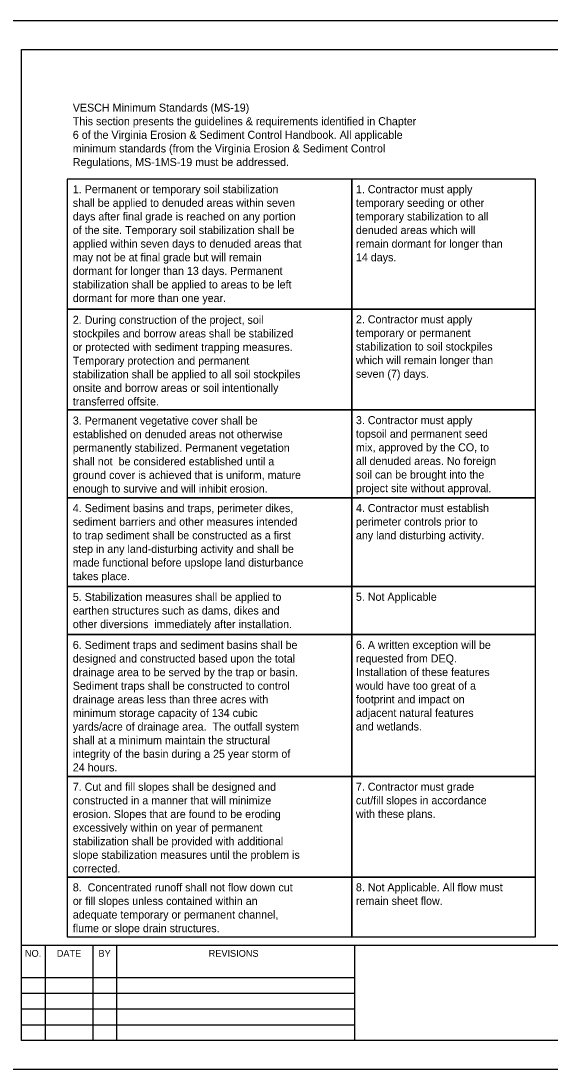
# Model space of a CAD drawing. Extents: x 20099.23 to 20103.48, y 6672.45 to 6674.37.
# Drawn here: x 20100.701 to 20101.165, y 6673.449 to 6674.366 of the extents above; entities that cross this region are included whole.
import ezdxf

# ---------------------------------------------------------------- set-up
doc = ezdxf.new("R2010")
doc.units = 0
for name, color, linetype in [('D_Details', 7, 'Continuous'), ('D_Plot_Shape', 7, 'Continuous'), ('D_Sheet', 7, 'Continuous')]:
    doc.layers.add(name, color=color, linetype=linetype)

msp = doc.modelspace()

# ---------------------------------------------------------------- linework, layer by layer
at = {"layer": 'D_Details'}
for points in [[(20100.99113, 6674.22774), (20100.74194, 6674.22774), (20100.74194, 6674.11395), (20100.99113, 6674.11395)], [(20101.15216, 6674.22774), (20100.99113, 6674.22774), (20100.99113, 6674.11395), (20101.15216, 6674.11395)], [(20100.99113, 6674.11395), (20100.74194, 6674.11395), (20100.74194, 6674.02578), (20100.99113, 6674.02578)], [(20101.15216, 6674.11395), (20100.99113, 6674.11395), (20100.99113, 6674.02578), (20101.15216, 6674.02578)], [(20100.99113, 6674.02578), (20100.74194, 6674.02578), (20100.74194, 6673.94888), (20100.99113, 6673.94888)], [(20101.15216, 6674.02578), (20100.99113, 6674.02578), (20100.99113, 6673.94888), (20101.15216, 6673.94888)], [(20100.99113, 6673.94888), (20100.74194, 6673.94888), (20100.74194, 6673.87127), (20100.99113, 6673.87127)], [(20101.15216, 6673.94888), (20100.99113, 6673.94888), (20100.99113, 6673.87127), (20101.15216, 6673.87127)], [(20100.99113, 6673.87127), (20100.74194, 6673.87127), (20100.74194, 6673.82925), (20100.99113, 6673.82925)], [(20101.15216, 6673.87127), (20100.99113, 6673.87127), (20100.99113, 6673.82925), (20101.15216, 6673.82925)], [(20100.99113, 6673.82925), (20100.74194, 6673.82925), (20100.74194, 6673.70518), (20100.99113, 6673.70518)], [(20101.15216, 6673.82925), (20100.99113, 6673.82925), (20100.99113, 6673.70518), (20101.15216, 6673.70518)], [(20100.99113, 6673.70518), (20100.74194, 6673.70518), (20100.74194, 6673.61724), (20100.99113, 6673.61724)], [(20101.15216, 6673.70518), (20100.99113, 6673.70518), (20100.99113, 6673.61724), (20101.15216, 6673.61724)], [(20100.99113, 6673.61724), (20100.74194, 6673.61724), (20100.74194, 6673.56499), (20100.99113, 6673.56499)], [(20101.15216, 6673.61724), (20100.99113, 6673.61724), (20100.99113, 6673.56499), (20101.15216, 6673.56499)]]:
    msp.add_lwpolyline(points, close=True, dxfattribs=at)
at = {"layer": 'D_Plot_Shape'}
msp.add_lwpolyline([(20102.06018, 6674.36597), (20100.64352, 6674.36597), (20100.64352, 6673.44931), (20102.06018, 6673.44931)], close=True, dxfattribs=at)
at = {"layer": 'D_Sheet'}
for p, q in [((20100.70185, 6673.55764), (20102.00185, 6673.55764)), ((20100.72269, 6673.55764), (20100.72269, 6673.47431)), ((20100.76435, 6673.55764), (20100.76435, 6673.47431)), ((20100.78519, 6673.55764), (20100.78519, 6673.47431)), ((20100.99352, 6673.55764), (20100.99352, 6673.47431)), ((20100.70185, 6673.52951), (20100.99352, 6673.52951)), ((20100.70185, 6673.51571), (20100.99352, 6673.51571)), ((20100.70185, 6673.50191), (20100.99352, 6673.50191)), ((20100.70185, 6673.48811), (20100.99352, 6673.48811))]:
    msp.add_line(p, q, dxfattribs=at)
msp.add_lwpolyline([(20100.70185, 6673.47431), (20100.70185, 6673.55764), (20100.70185, 6674.34097), (20102.00185, 6674.34097), (20102.00185, 6673.55764), (20102.00185, 6673.47431), (20100.70185, 6673.47431)], dxfattribs=at)

# ---------------------------------------------------------------- texts
at = {"layer": 'D_Details'}
for s, p in [('VESCH Minimum Standards (MS-19)', (20100.74688, 6674.28668)), ('This section presents the guidelines & requirements identified in Chapter ', (20100.74688, 6674.27478)), ('6 of the Virginia Erosion & Sediment Control Handbook. All applicable ', (20100.74688, 6674.26288)), ('minimum standards (from the Virginia Erosion & Sediment Control ', (20100.74688, 6674.25098)), ('Regulations, MS-1MS-19 must be addressed.', (20100.74688, 6674.23908)), ('1. Permanent or temporary soil stabilization ', (20100.74688, 6674.21531)), ('1. Contractor must apply ', (20100.99479, 6674.2153)), ('shall be applied to denuded areas within seven ', (20100.74688, 6674.20341)), ('temporary seeding or other ', (20100.99479, 6674.2034)), ('days after final grade is reached on any portion ', (20100.74688, 6674.19151)), ('temporary stabilization to all ', (20100.99479, 6674.1915)), ('of the site. Temporary soil stabilization shall be ', (20100.74688, 6674.17961)), ('denuded areas which will ', (20100.99479, 6674.1796)), ('applied within seven days to denuded areas that ', (20100.74688, 6674.16771)), ('remain dormant for longer than ', (20100.99479, 6674.1677)), ('may not be at final grade but will remain ', (20100.74688, 6674.15581)), ('14 days.', (20100.99479, 6674.1558)), ('dormant for longer than 13 days. Permanent ', (20100.74688, 6674.14391)), ('stabilization shall be applied to areas to be left ', (20100.74688, 6674.13201)), ('dormant for more than one year. ', (20100.74688, 6674.12011)), ('2. During construction of the project, soil ', (20100.74688, 6674.10108)), ('2. Contractor must apply ', (20100.99479, 6674.10151)), ('stockpiles and borrow areas shall be stabilized ', (20100.74688, 6674.08918)), ('temporary or permanent ', (20100.99479, 6674.08961)), ('or protected with sediment trapping measures. ', (20100.74688, 6674.07728)), ('stabilization to soil stockpiles ', (20100.99479, 6674.07771)), ('Temporary protection and permanent ', (20100.74688, 6674.06538)), ('which will remain longer than ', (20100.99479, 6674.06581)), ('stabilization shall be applied to all soil stockpiles ', (20100.74688, 6674.05348)), ('seven (7) days.', (20100.99479, 6674.05391)), ('onsite and borrow areas or soil intentionally ', (20100.74688, 6674.04158)), ('transferred offsite.', (20100.74688, 6674.02968)), ('3. Permanent vegetative cover shall be ', (20100.74688, 6674.01297)), ('3. Contractor must apply ', (20100.99479, 6674.01334)), ('established on denuded areas not otherwise ', (20100.74688, 6674.00107)), ('topsoil and permanent seed ', (20100.99479, 6674.00144)), ('permanently stabilized. Permanent vegetation ', (20100.74688, 6673.98917)), ('mix, approved by the CO, to ', (20100.99479, 6673.98954)), ('shall not  be considered established until a ', (20100.74688, 6673.97727)), ('all denuded areas. No foreign ', (20100.99479, 6673.97764)), ('ground cover is achieved that is uniform, mature ', (20100.74688, 6673.96537)), ('soil can be brought into the ', (20100.99479, 6673.96574)), ('enough to survive and will inhibit erosion.', (20100.74688, 6673.95347)), ('project site without approval. ', (20100.99479, 6673.95384)), ('4. Sediment basins and traps, perimeter dikes, ', (20100.74688, 6673.9364)), ('4. Contractor must establish ', (20100.99479, 6673.93644)), ('sediment barriers and other measures intended ', (20100.74688, 6673.9245)), ('perimeter controls prior to ', (20100.99479, 6673.92454)), ('to trap sediment shall be constructed as a first ', (20100.74688, 6673.9126)), ('any land disturbing activity.', (20100.99479, 6673.91264)), ('step in any land-disturbing activity and shall be ', (20100.74688, 6673.9007)), ('made functional before upslope land disturbance ', (20100.74688, 6673.8888)), ('takes place. ', (20100.74688, 6673.8769)), ('5. Stabilization measures shall be applied to ', (20100.74688, 6673.85873)), ('5. Not Applicable', (20100.99479, 6673.85883)), ('earthen structures such as dams, dikes and ', (20100.74688, 6673.84683)), ('other diversions  immediately after installation. ', (20100.74688, 6673.83493)), ('6. A written exception will be ', (20100.99479, 6673.81681)), ('6. Sediment traps and sediment basins shall be ', (20100.74688, 6673.81672)), ('designed and constructed based upon the total ', (20100.74688, 6673.80482)), ('requested from DEQ. ', (20100.99479, 6673.80491)), ('drainage area to be served by the trap or basin. ', (20100.74688, 6673.79292)), ('Installation of these features ', (20100.99479, 6673.79301)), ('Sediment traps shall be constructed to control ', (20100.74688, 6673.78102)), ('would have too great of a ', (20100.99479, 6673.78111)), ('drainage areas less than three acres with ', (20100.74688, 6673.76912)), ('footprint and impact on ', (20100.99479, 6673.76921)), ('minimum storage capacity of 134 cubic ', (20100.74688, 6673.75722)), ('adjacent natural features ', (20100.99479, 6673.75731)), ('yards/acre of drainage area.  The outfall system ', (20100.74688, 6673.74532)), ('and wetlands. ', (20100.99479, 6673.74541)), ('shall at a minimum maintain the structural ', (20100.74688, 6673.73342)), ('integrity of the basin during a 25 year storm of ', (20100.74688, 6673.72152)), ('24 hours. ', (20100.74688, 6673.70962)), ('7. Cut and fill slopes shall be designed and ', (20100.74688, 6673.69265)), ('7. Contractor must grade ', (20100.99479, 6673.69274)), ('constructed in a manner that will minimize ', (20100.74688, 6673.68075)), ('cut/fill slopes in accordance ', (20100.99479, 6673.68084)), ('erosion. Slopes that are found to be eroding ', (20100.74688, 6673.66885)), ('with these plans.', (20100.99479, 6673.66894)), ('excessively within on year of permanent ', (20100.74688, 6673.65695)), ('stabilization shall be provided with additional ', (20100.74688, 6673.64505)), ('slope stabilization measures until the problem is ', (20100.74688, 6673.63315)), ('corrected.', (20100.74688, 6673.62125)), ('8.  Concentrated runoff shall not flow down cut ', (20100.74688, 6673.6047)), ('8. Not Applicable. All flow must ', (20100.99479, 6673.6048)), ('or fill slopes unless contained within an ', (20100.74688, 6673.5928)), ('remain sheet flow.', (20100.99479, 6673.5929)), ('adequate temporary or permanent channel, ', (20100.74688, 6673.5809)), ('flume or slope drain structures. ', (20100.74688, 6673.569))]:
    msp.add_text(s, height=0.007, dxfattribs=at).set_placement(p)
at = {"layer": 'D_Sheet'}
for s, p in [('NO.', (20100.70495, 6673.54748)), ('DATE', (20100.73284, 6673.54748)), ('BY', (20100.76941, 6673.54748)), ('REVISIONS', (20100.86584, 6673.54748))]:
    msp.add_text(s, height=0.006, dxfattribs=at).set_placement(p)

doc.saveas('drawing.dxf')
